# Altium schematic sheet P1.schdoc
size 297 x 210 mm; Device: Sheet-Symbol_A4; Symbol: Sheet-Symbol_A4; Company: 嘉立创EDA; Version: V1.0; Page Size: A4; @Project Name: stm32f4; @Page Count: 1; @Update Date: 2025-11-13; @Create Date: 2025-11-13; @Schematic Name: TP5400电源板-v1.1; @Page No: 1; @Page Name: P1; @Board Name: TP5400电源板-v1.1; @Create Time: 15:17:01; @Update Time: 23:17:01
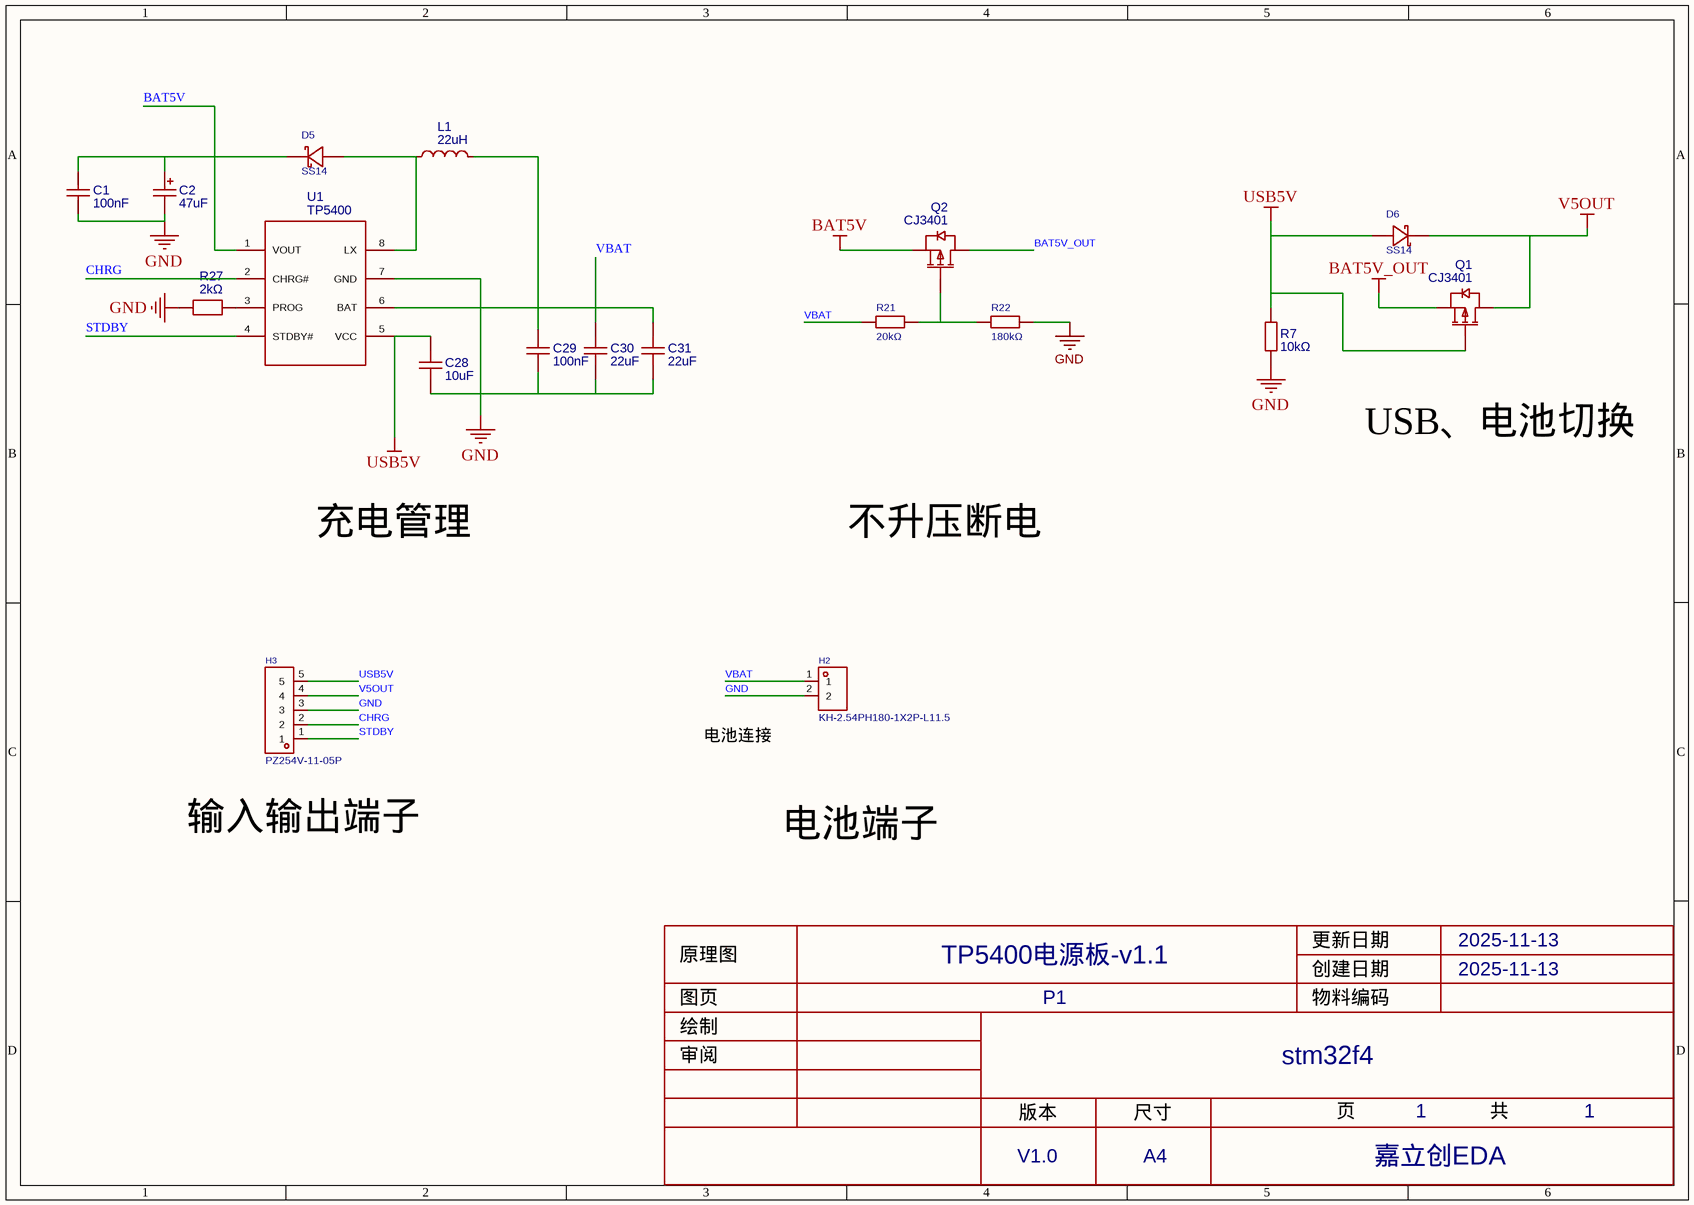
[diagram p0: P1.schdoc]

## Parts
C1  100nF  [C0805_1]
C2  47uF  [CASE-B_3528]
C28  10uF  [C0805_1]
C29  100nF  [C0805_1]
C30  22uF  [C0805_1]
C31  22uF  [C0805_1]
D5  SS14  [SOD-123FL_L2.8-W1.8-LS3.7-RD]
D6  SS14  [SOD-123FL_L2.8-W1.8-LS3.7-RD]
H2  KH-2.54PH180-1X2P-L11.5  [HDR-TH_2P-P2.54-V-M_1]
H3  PZ254V-11-05P  [HDR-TH_5P-P2.54-V-M_1]
L1  22uH  [IND-SMD_L4.5-W4.0_SCCD43]
Q1  CJ3401  [SOT-23-3_L2.9-W1.6-P1.90-LS2.8-BR_1]
Q2  CJ3401  [SOT-23-3_L2.9-W1.6-P1.90-LS2.8-BR_1]
R7  10kΩ  [R0805_1]
R21  20kΩ  [R0805_1]
R22  180kΩ  [R0805_1]
R27  2kΩ  [R0805_1]
U1  TP5400  [ESOP-8_L4.9-W3.9-P1.27-LS6.0-BL-EP]

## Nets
BAT5V: C1.2 C2.1 D5.1(A) Q2.2(S) U1.1(VOUT)
BAT5V_OUT: Q1.2(S) Q2.3(D)
GND: C1.1 C2.2 C28.2 C29.1 C30.1 C31.1 H2.2 H3.3 R7.1 R22.2 R27.1 U1.7(GND)
USB5V: C28.1 D6.2(K) H3.5 Q1.1(G) R7.2 U1.5(VCC)
V5OUT: D6.1(A) H3.4 Q1.3(D)
CHRG: H3.2 U1.2(CHRG#)
STDBY: H3.1 U1.4(STDBY#)
VBAT: C29.2 C30.2 C31.2 H2.1 L1.2 R21.1 U1.6(BAT)
NetD5_2: D5.2(K) L1.1 U1.8(LX)
NetQ2_1: Q2.1(G) R21.2 R22.1
NetR27_2: R27.2 U1.3(PROG)

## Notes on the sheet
- USB、电池切换
- 充电管理
- 不升压断电
- 电池连接
- 输入输出端子
- 电池端子

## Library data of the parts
C1 C29 = CL21B104KBCNNNC: Manufacturer: SAMSUNG(三星); Origin Footprint: C0805; Convert to PCB: yes; Tolerance: ±10%; Voltage Rated: 50V; Temperature Coefficient: X7R; ModelId: 1ba041120af144c991958decab20d241; ModelName: C0805_L2.0-W1.3-H1.3; ModelTransform: 78.74,51.181,0,0,0,0,0,0.0005,0
C2 = CA45-B-10V-47uF-K: Manufacturer: CEC(振华新云); Origin Footprint: CAP-SMD_L3.5-W2.8-R-RD; Convert to PCB: yes; Tolerance: ±10%; Rated Voltage: 10V; Equivalent Series Resistance(ESR): 2.4Ω@100kHz; ModelId: b77bd53aeda446d2bdd09b0fdaf9418a; ModelName: CASE-B_L3.5-W2.8-H1.9; ModelTransform: 145.669,110.236,0,0,0,0,0,0,0
C28 = 0805F106M160NT: Manufacturer: FH(风华); Origin Footprint: C0805; Convert to PCB: yes; Tolerance: ±20%; Voltage Rated: 16V; Temperature Coefficient: Y5V; ModelId: 1ba041120af144c991958decab20d241; ModelName: C0805_L2.0-W1.3-H1.3; ModelTransform: 78.74,51.181,0,0,0,0,0,0.0005,0
C30 C31 = CL21A226MAQNNNE_C45783: Manufacturer: SAMSUNG(三星); Origin Footprint: C0805; Convert to PCB: yes; Tolerance: ±20%; Voltage Rated: 25V; Temperature Coefficient: X5R; ModelId: 1ba041120af144c991958decab20d241; ModelName: C0805_L2.0-W1.3-H1.3; ModelTransform: 78.74,51.181,0,0,0,0,0,0.0005,0
D5 D6 = SS14_C2909920: Manufacturer: KUU; AddInBom: yes; Reverse Voltage (Vr): 40V; Average Rectified Current (Io): 1A; Forward Voltage (Vf@If): 550mV@1A; Reverse Leakage Current (Ir): 500uA@40V; ModelId: b8c4b3388b3d4c198b22b876116f592b; ModelTransform: 145.669,70.866,0,0,0,0,0,0,0
H2 = KH-2.54PH180-1X2P-L11.5: Manufacturer: kinghelm(金航标); AddInBom: yes; Pitch: 2.54mm; Pin Structure: 1x2P; Circluar Pins/Square Pins: 方针; Current Rating (Max): 3A; ModelId: e35305ec3aa84b66b849f914b715e73f; ModelName: HDR2.54-M-LI-1X2P; ModelTransform: 200,100,0,0,0,0,0,0,-118.11
H3 = PZ254V-11-05P_1: Manufacturer: XFCN(兴飞); AddInBom: yes; Pitch: 2.54mm; Pin Structure: 1x5P; Circluar Pins/Square Pins: 方针; ModelId: 47d466e4a34f4fc5bc626cf773a24dd5; ModelName: HDR-TH_5P-P2.54-M-LI-1X5P; ModelTransform: 499.999,100,0,0,0,0,0,0,-118.11
L1 = SCCD43-220KT: Manufacturer: Yanchuang(研创); Convert to PCB: yes; ModelId: 979f186bb2ed46c794684c7f6ad4b7fcuser; ModelName: SPR_IND-SMD_L4.5-W4.0_(XRCD43_H3.2-W4.0_L4.5); ModelTransform: 157.48,170.22,126.38,0,0,0,0,0,0
Q1 = CJ3401: Manufacturer: CJ(江苏长电/长晶); Origin Footprint: SOT-23-3_L2.9-W1.6-P1.90-LS2.8-BR; Convert to PCB: yes; Type: P沟道; Drain Source Voltage (Vdss): 30V; Continuous Drain Current (Id): 4.2A; Power Dissipation (Pd): 350mW; Drain Source On Resistance (RDS(on)@Vgs,Id): 65mΩ@10V,4.2A; Gate Threshold Voltage (Vgs(th)@Id): 1.3V@250uA; ModelId: 89cb27a44ab2466697082bb9fd73a7d0; ModelName: SOT-23-3L_L2.9-W1.6-H1.1-LS2.8-P0.95; ModelTransform: 110.236,114.173,0,180,0,0,-0.005,0.0005,0
Q2 = CJ3401: Manufacturer: CJ; Origin Footprint: SOT-23-3_L2.9-W1.6-P1.90-LS2.8-BR; Convert to PCB: yes
R7 = AC0805FR-0710KL: Manufacturer: YAGEO(国巨); Symbol: 10K; Origin Footprint: R0805; Convert to PCB: yes; Tolerance: ±1%; Power(Watts): 125mW; Temperature Coefficient: ±100ppm/℃; Overload Voltage (Max): 150V; ModelId: 37a81e68749a4138bd2dfa6897b24b85; ModelName: R0805_L2.0-W1.3-H0.6; ModelTransform: 78.74,51.181,0,0,0,0,0,-0.0005,0
R21 = 0805W8F2002T5E: Manufacturer: UNI-ROYAL(厚声); AddInBom: yes; Tolerance: ±1%; Power(Watts): 125mW; Temperature Coefficient: ±100ppm/℃; Overload Voltage (Max): 150V; ModelId: 37a81e68749a4138bd2dfa6897b24b85; ModelName: R0805_L2.0-W1.3-H0.6; ModelTransform: 78.74,51.181,0,0,0,0,0,-0.0005,0
R22 = 0805W8F1803T5E: Manufacturer: UNI-ROYAL(厚声); AddInBom: yes; Tolerance: ±1%; Power(Watts): 125mW; Temperature Coefficient: ±100ppm/℃; Overload Voltage (Max): 150V; ModelId: 37a81e68749a4138bd2dfa6897b24b85; ModelName: R0805_L2.0-W1.3-H0.6; ModelTransform: 78.74,51.181,0,0,0,0,0,-0.0005,0
R27 = MR08X2001FTL: Manufacturer: Walsin(华新科); Resistance: 2K; Origin Footprint: R0805; Convert to PCB: yes; Tolerance: ±1%; Power(Watts): 250mW; Temperature Coefficient: ±100ppm/℃; Overload Voltage (Max): 150V; ModelId: 37a81e68749a4138bd2dfa6897b24b85; ModelName: R0805_L2.0-W1.3-H0.6; ModelTransform: 78.74,51.181,0,0,0,0,0,-0.0005,0
U1 = TP5400: 锂电池充电，升压二合一芯片，南京拓品微电子有限公司生产; Manufacturer: TOPPOWER(南京拓微); Origin Footprint: SOIC-8_L5.0-W4.0-P1.27-LS6.0-BL-EP; Convert to PCB: yes; ModelId: d3e00daa36c445139c055a3b9efb85d2; ModelName: ESOP-8_L4.9-W3.9-H1.6-LS6.0-P1.27; ModelTransform: 240.157,192.913,0,90,0,0,0,0,0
